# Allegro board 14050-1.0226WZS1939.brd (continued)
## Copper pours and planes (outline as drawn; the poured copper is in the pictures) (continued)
1D35V_VGA_S0 on TOP: 50.88,96.26 50.75,96.39 48.62,96.39 48.54,96.46 48.54,96.97 48.64,97.07 50.35,97.07 50.47,97.2 50.47,98.09 50.29,98.28 48.82,98.28 48.7,98.4 48.7,108.06 48.79,108.15 50.22,108.15 50.37,108 50.37,105.8 50.94,105.22 50.94,103.41 50.78,103.24 50.77,103.24 50.36,102.84 50.36,101.84 49.97,101.45 49.97,99.67 50.23,99.41 50.8,99.41 50.98,99.59 50.98,100.93 51.11,101.06 51.87,101.06 52.71,100.22 52.71,96.67 52.3,96.26 ; 9 cut-outs
1D35V_VGA_S0 on TOP: 58.07,73.15 56.17,75.06 53.5,75.06 51.47,77.09 49.94,77.09 48.42,78.61 48.42,85.6 48.45,85.63 48.45,86.39 48.39,86.46 48.39,87.62 48.59,87.83 48.59,90.85 48.7,90.95 49.33,90.95 49.76,91.38 51.11,91.38 51.64,90.85 51.64,90.01 53.09,88.56 53.09,87.52 52.58,87.01 51.87,87.01 51.21,86.36 51.21,83.19 53.37,81.03 62.01,81.03 62.39,80.64 62.39,78.36 63.66,77.09 65.44,77.09 65.57,76.96 65.57,73.79 64.93,73.15 ; 9 cut-outs
1D35V_VGA_S0 on BOTTOM: 48.55,83.44 48.42,83.57 48.42,85.93 48.59,86.1 48.59,90.04 48.95,90.4 48.95,90.82 49.13,91 49.62,91 49.99,90.63 50.86,90.63 50.86,90.65 51.37,91.16 52.17,91.16 52.66,90.67 52.66,89.55 52.17,89.07 51.64,89.07 51.46,88.89 51.46,88.21 51.87,87.8 52.48,87.8 52.86,88.18 53.29,88.18 53.44,88.03 53.44,86.38 53.29,86.23 53.09,86.23 52.58,86.74 51.92,86.74 51.64,86.46 51.64,85.85 51.87,85.62 52.12,85.62 52.3,85.8 52.66,85.8 52.73,85.72 52.73,84.6 52.75,84.59 52.75,83.7 52.48,83.44 ; 3 cut-outs
1D35V_VGA_S0 on BOTTOM: 52,94.97 50.57,96.39 48.77,96.39 48.59,96.57 48.59,99.23 48.77,99.41 50.5,99.41 50.68,99.59 50.68,100.12 48.85,101.95 48.85,105.86 49.05,106.06 50.8,106.06 51.18,105.68 51.18,101.65 52.61,100.22 52.61,95.17 52.4,94.97 ; 1 cut-out
1D35V_VGA_S0 on BOTTOM: 48.7,111.99 48.57,112.12 48.57,118.34 48.84,118.61 50.42,118.61 50.55,118.49 50.55,114.17 49.44,113.06 49.44,112.22 49.21,111.99 ; 5 cut-outs
1D35V_VGA_S0 on BOTTOM: 60.51,89.39 60.51,91.42 61.78,92.69 61.78,96.75 61.93,96.9 61.93,96.93 61.96,96.95 62.52,96.95 62.75,97.18 62.75,98.3 62.54,98.5 62.54,99.42 61.52,100.44 61.52,103.61 58.73,106.41 58.73,108.31 58.86,108.44 59.24,108.44 61.4,106.28 61.4,106.15 62.92,104.63 62.92,103.1 63.79,102.23 63.79,101.98 64.04,101.73 64.93,101.73 65.54,102.34 66.48,102.34 67.49,101.33 71.94,101.33 72.19,101.58 72.19,103.89 72.6,104.3 76.05,104.3 76.51,104.75 76.51,106.02 76.64,106.15 77.91,106.15 78.16,106.41 78.92,106.41 79.05,106.28 79.05,104.12 78.67,103.74 78.67,97.52 78.8,97.39 78.8,93.83 78.42,93.45 77.78,93.45 77.02,92.69 71.05,92.69 70.6,93.13 64.76,93.13 61.02,89.39 ; 14 cut-outs
1D35V_VGA_S0 on L3: 52.25,83.79 49.93,86.11 49.56,86.11 48.04,87.63 48.04,99.31 48.17,99.44 48.17,122.68 49.31,123.83 52.61,123.83 53.25,123.19 53.25,116.08 52.23,115.06 52.23,114.68 52.1,114.55 52.1,112.01 51.98,111.89 50.96,111.89 50.83,111.76 50.83,110.24 52.23,108.84 52.23,105.54 51.21,104.52 51.21,102.36 51.98,101.6 51.98,98.68 51.85,98.68 50.96,97.79 50.96,97.28 51.21,97.03 51.85,97.03 51.98,96.9 51.98,96.65 51.85,96.52 51.6,96.52 50.58,95.5 50.58,94.87 49.94,94.23 49.94,91.57 50.33,91.19 51.74,91.19 52.38,90.55 52.38,88.23 52.89,87.73 52.89,85.31 53.39,84.81 55.55,84.81 57.08,86.33 57.71,86.33 58.35,85.69 58.35,84.43 57.7,83.79
1D35V_VGA_S0 on L4: 48.17,83.06 47.6,83.62 47.6,116.22 49.31,117.93 49.31,123.44 49.82,123.95 51.72,123.95 53.12,122.56 66.58,122.56 69.12,120.02 71.28,120.02 79.43,111.86 79.43,106.41 79.43,106.4 79.43,101.98 79.41,101.96 79.41,98.68 82.86,95.23 84.11,95.23 84.62,94.72 84.62,92.08 86.14,90.55 86.14,90.42 86.16,90.4 86.16,85.8 81.31,80.95 74.03,80.95 73.96,80.89 54.91,80.89 52.74,83.06 ; 1 cut-out
62883AGND on BOTTOM: 122.97,71.37 122.84,71.5 122.84,72.52 122.72,72.64 118.78,72.64 118.65,72.52 118.65,71.75 118.52,71.63 117.89,71.63 117.76,71.75 117.76,76.45 118.65,77.34 122.72,77.34 122.84,77.22 122.84,75.18 123.99,74.04 123.99,71.5 123.86,71.37 ; 13 cut-outs
AD+_2 on TOP: 66.58,30.73 66.33,30.99 66.33,34.04 67.6,35.31 67.6,37.21 67.72,37.34 68.61,37.34 68.74,37.21 68.74,31.24 68.23,30.73 ; 6 cut-outs
AD+_TO_SYS on TOP: 57.18,40.26 56.55,40.89 53.75,40.89 53.63,41.02 53.63,42.04 52.87,42.8 52.87,46.23 53.25,46.61 57.18,46.61 57.31,46.48 57.31,45.34 57.44,45.21 57.82,45.21 57.95,45.34 57.95,46.48 58.07,46.61 59.09,46.61 59.22,46.48 59.22,40.39 59.09,40.26 ; 1 cut-out
AD+_TO_SYS on BOTTOM: 56.8,38.86 56.68,38.99 56.68,46.48 56.8,46.61 59.22,46.61 59.34,46.48 59.34,38.99 59.22,38.86
AD_JK on TOP: 54.39,23.5 53.5,24.38 53.5,28.19 54.01,28.7 54.9,28.7 56.29,30.1 56.29,30.86 56.55,31.11 56.55,38.61 56.68,38.73 62.01,38.73 63.41,37.34 67.22,37.34 67.34,37.21 67.34,35.56 66.07,34.29 66.07,27.43 65.44,26.8 61.88,26.8 60.23,25.15 60.23,24.38 59.34,23.5 ; 8 cut-outs
AD_JK on BOTTOM: 54.01,20.57 53.5,21.08 53.5,28.7 53.63,28.83 55.02,28.83 55.53,29.34 55.53,30.73 56.42,31.62 59.47,31.62 59.72,31.37 66.33,31.37 66.45,31.24 66.45,28.19 58.83,20.57
AD_JK on L3: 53.75,32.13 64.68,32.13 65.44,31.37 65.44,29.21 60.36,24.13 54.01,24.13 53.25,24.89 53.25,31.62
AD_JK on L4: 53.5,31.75 64.8,31.75 65.44,31.11 65.44,29.59 60.1,24.26 53.88,24.26 53.25,24.89 53.25,31.5
AUD_DVDD on TOP: 162.29,81.89 162.16,82.02 162.16,83.52 161.63,84.05 160.82,84.05 160.64,84.23 160.64,84.89 160.43,85.09 160.05,85.09 159.93,85.22 159.93,87.1 160.05,87.22 161.98,87.22 162.1,87.11 162.1,85.1 163.18,84.02 163.18,82.3 162.77,81.89 ; 2 cut-outs
BOOT1_PHASE1 on TOP: 121.95,80.77 121.7,81.03 121.7,81.79 121.83,81.92 123.99,81.92 124.11,81.79 124.11,80.9 123.99,80.77
BT+ on TOP: 48.29,61.09 47.02,62.36 42.45,62.36 40.42,64.39 37.37,64.39 37.24,64.52 37.24,66.93 36.99,67.18 30.64,67.18 30.51,67.31 30.51,71.25 30.64,71.37 39.61,71.37 40.34,70.64 41.54,70.64 41.82,70.36 41.82,66.67 42.32,66.17 48.55,66.17 50.2,64.52 51.72,64.52 51.85,64.39 51.85,61.21 51.72,61.09 ; 4 cut-outs
BT+ on BOTTOM: 48.93,61.21 48.67,61.47 48.67,65.28 48.8,65.41 49.82,65.41 50.07,65.66 50.96,65.66 51.85,64.77 51.85,61.47 51.6,61.21
BT+ on BOTTOM: 34.22,68.02 33.84,68.4 33.84,71.12 34.09,71.37 36.81,71.37 37.09,71.09 37.09,68.25 36.86,68.02 ; 2 cut-outs
BT+_R on BOTTOM: 46.9,61.59 45.88,62.61 40.93,62.61 40.67,62.87 40.67,65.66 40.93,65.91 46.52,65.91 47.02,65.41 48.04,65.41 48.17,65.28 48.17,61.72 48.04,61.59
CAGND on TOP: 34.32,29.84 33.43,30.73 33.43,34.8 33.69,35.05 35.72,35.05 36.23,35.56 36.23,38.35 36.36,38.48 38.46,38.48 38.84,38.86 38.84,39.7 39.02,39.88 40.37,39.88 40.5,39.75 40.5,37.52 40.27,37.29 40.27,36.63 40.65,36.25 40.65,34.29 41.13,33.81 41.13,33.35 41.05,33.27 40.6,33.27 39.76,34.11 39.76,34.8 39.5,35.05 37.88,35.05 36.74,33.91 35.85,33.91 35.34,33.4 35.34,32.13 35.59,31.88 37.88,31.88 38.01,31.75 38.01,30.35 37.5,29.84 ; 17 cut-outs
CPU_VCORE on TOP: 41.94,171.7 38.62,175.03 35.44,175.03 35.21,175.26 35.21,178.13 35.64,178.56 42.2,178.56 42.58,178.94 42.58,180.21 45.18,182.82 47.72,182.82 48.17,183.26 48.17,185.8 48.52,186.16 59.47,186.16 60.36,185.27 60.36,179.96 52.1,171.7
CPU_VCORE on BOTTOM: 73.69,156.84 73.57,156.97 73.57,168.4 73.69,168.53 88.55,168.53 88.68,168.4 88.68,159.64 88.55,159.51 78.39,159.51 75.73,156.84 ; 33 cut-outs
CPU_VCORE on L3: 77.88,167 77.88,159.64 78.14,159.38 88.04,159.38 88.17,159.51 88.17,167 88.04,167.13 78.01,167.13
CPU_VCORE on L4: 75.47,175.39 87.28,175.39 88.43,174.24 88.43,159.51 88.17,159.26 77.88,159.26 75.6,156.97 74.58,156.97 74.33,157.23 74.33,157.35 62.9,168.78 50.96,168.78 49.56,170.18 49.56,183.9 49.58,183.91 49.58,185.33 50.17,185.93 64.93,185.93
DC_19V on TOP: 59.85,39.12 59.72,39.24 59.72,46.35 59.98,46.61 63.15,46.61 63.41,46.35 63.41,43.94 63.53,43.81 68.61,43.81 68.74,43.69 68.74,39.24 68.61,39.12 ; 4 cut-outs
DC_19V on TOP: 42.53,70.31 42.37,70.46 42.37,71.35 42.68,71.65 42.68,72.54 42.81,72.67 43.8,72.67 44.53,71.93 48.65,71.93 48.72,71.86 48.72,70.71 48.32,70.31 ; 3 cut-outs
DC_19V on BOTTOM: 59.98,38.86 59.85,38.99 59.85,46.35 59.98,46.48 63.03,46.48 63.53,45.97 63.53,39.62 62.77,38.86
DCBATOUT on TOP: 112.17,19.68 111.03,20.83 111.03,26.92 111.29,27.18 114.08,27.18 114.21,27.05 114.21,19.81 114.08,19.68
DCBATOUT on TOP: 97.44,57.4 94.65,60.2 90.46,60.2 88.81,61.85 88.81,64.9 88.93,65.02 90.46,65.02 90.58,64.9 90.58,62.87 91.47,61.98 95.92,61.98 98.59,59.31 103.67,59.31 103.79,59.18 103.79,57.48 103.72,57.4
DCBATOUT on TOP: 51.09,46.48 50.71,46.86 50.71,50.62 50.96,50.88 55.68,50.88 57.56,49 57.56,47.37 57.31,47.12 53.12,47.12 52.48,46.48 ; 1 cut-out
DCBATOUT on TOP: 42.32,66.67 42.07,66.93 42.07,69.65 42.43,70 48.65,70 48.93,69.72 48.93,67.06 48.55,66.67 ; 2 cut-outs
DCBATOUT on TOP: 7.02,151.13 6.89,151.26 6.89,154.31 10.45,157.86 10.45,162.18 7.53,165.1 7.53,167.77 9.69,169.93 12.99,169.93 13.37,169.54 13.37,161.93 14.13,161.16 14.13,159 13.11,157.99 13.11,151.26 12.99,151.13
DCBATOUT on TOP: 38.54,52.3 38.29,52.55 38.29,58.37 38.46,58.55 42.27,58.55 42.53,58.29 42.53,54.38 42.81,54.1 42.81,52.5 42.6,52.3 ; 2 cut-outs
DCBATOUT on TOP: 121.32,86.23 121.19,86.36 121.19,91.69 122.21,92.71 122.21,97.54 122.33,97.66 128.68,97.66 129.07,98.04 129.07,99.31 129.57,99.82 133.26,99.82 133.64,99.44 133.64,95.76 133.89,95.5 139.23,95.5 139.35,95.38 139.35,90.17 139.23,90.04 138.46,90.04 138.08,89.66 138.08,87.63 137.96,87.5 135.54,87.5 134.34,86.3 125.19,86.3 125.13,86.23 ; 4 cut-outs
DCBATOUT on TOP: 49.03,127.18 46.06,130.15 46.06,131.57 46.97,132.49 55.94,132.49 56.55,131.88 56.55,127.69 56.04,127.18
DCBATOUT on TOP: 68.51,26.19 68.33,26.37 68.33,28.93 68.82,29.41 69.76,29.41 70.09,29.08 70.09,26.44 69.83,26.19 ; 2 cut-outs
DCBATOUT on TOP: 22.44,162.31 21.88,162.86 21.88,166.17 22.13,166.42 24.65,166.42 25.05,166.01 25.05,162.56 24.8,162.31
DCBATOUT on TOP: 67.95,44.42 66.84,45.54 66.15,45.54 65.87,45.82 65.87,47.29 66.78,48.21 69.25,48.21 69.6,47.85 69.6,44.91 69.12,44.42 ; 1 cut-out
DCBATOUT on TOP: 19.21,191.52 19.08,191.64 19.08,201.68 19.34,201.93 22.64,201.93 22.89,202.18 22.89,208.91 23.4,209.42 40.04,209.42 42.4,211.79 42.4,218.44 42.55,218.59 48.57,218.59 48.93,218.24 48.93,209.68 46.9,207.65 46.9,202.06 50.07,202.06 50.2,201.93 50.2,191.64 50.07,191.52 44.74,191.52 44.61,191.64 44.61,196.22 41.56,199.26 41.56,202.44 41.18,202.82 28.1,202.82 27.59,202.31 27.59,198.88 24.93,196.22 24.93,191.64 24.8,191.52 ; 4 cut-outs
DCBATOUT on BOTTOM: 89.19,62.87 88.81,63.25 88.81,66.87 84.23,71.44 73.88,71.44 73.19,70.74 68.74,70.74 68.61,70.87 68.61,77.98 69.25,78.61 83.09,78.61 89.7,85.22 102.78,85.22 105.06,87.5 111.54,87.5 113.19,85.85 120.68,85.85 121.19,86.36 121.19,91.69 122.21,92.71 122.21,97.54 122.33,97.66 137.07,97.66 138.59,96.14 138.59,87.88 130.84,80.14 110.27,80.14 109.51,79.38 93,79.38 91.47,77.85 91.47,73.79 90.33,72.64 90.58,72.39 90.58,63.25 90.2,62.87 ; 6 cut-outs
DCBATOUT on BOTTOM: 113.32,4.32 113.19,4.45 113.19,20.32 111.03,22.48 111.03,26.8 111.16,26.92 117.76,26.92 118.52,26.16 118.52,14.1 119.54,13.08 119.54,9.78 117.76,8 117.76,4.39 117.69,4.32
DCBATOUT on BOTTOM: 36.99,51.94 36.86,52.07 36.86,53.04 38.21,54.38 42.93,54.38 42.96,54.36 42.96,52.07 42.83,51.94 ; 1 cut-out
DCBATOUT on BOTTOM: 16.67,163.19 16.29,163.58 12.73,163.58 8.92,167.39 8.92,168.66 9.94,169.67 9.94,186.31 14.13,190.5 14.13,195.58 20.99,202.44 20.99,206.5 21.5,207.01 35.34,207.01 37.37,209.04 39.66,209.04 42.45,211.84 42.45,218.72 43.26,219.53 48.83,219.53 49.31,219.05 49.31,216.66 49.69,216.28 49.69,215.39 50.2,214.88 54.14,214.88 54.26,214.76 54.26,209.42 54.14,209.3 50.07,209.3 49.82,209.04 49.82,197.74 49.44,197.36 41.31,197.36 41.18,197.49 41.18,202.31 40.8,202.69 28.61,202.69 28.23,202.31 28.23,195.83 23.15,190.75 23.15,188.09 20.48,185.42 20.48,171.2 23.78,167.89 23.78,163.58 23.4,163.19 ; 2 cut-outs
DCBATOUT on BOTTOM: 34.96,126.75 32.67,129.03 32.67,132.72 29.37,136.02 16.92,136.02 15.78,137.16 15.78,139.83 15.91,139.95 34.7,139.95 42.58,132.08 49.06,132.08 49.56,131.57 49.56,127 49.31,126.75
DCBATOUT on L3: 113.19,28.07 113.19,24.51 111.54,22.86 68.61,22.86 68.49,22.99 68.49,28.07 68.61,28.19 113.06,28.19
DCBATOUT on L3: 6.89,155.96 6.89,151.26 7.15,151 9.56,151 10.07,151.51 10.07,165.48 12.99,168.4 12.99,169.54 12.61,169.93 9.81,169.93 8.42,168.53 8.42,157.48
DCBATOUT on L3: 49.82,43.94 46.9,46.86 40.67,46.86 37.88,49.66 37.88,53.78 38.13,54.04 50.52,54.04 54.01,50.55 68.74,50.55 69.25,50.04 69.25,45.72 67.47,43.94
DCBATOUT on L4: 15.02,140.72 15.02,146.43 14.13,147.32 14.13,150.88 11.84,153.16 11.84,166.75 12.86,167.77 12.86,169.67 12.61,169.93 9.56,169.93 8.67,169.04 7.02,169.04 6.64,168.66 6.64,163.83 8.67,161.8 8.67,158.12 6.64,156.08 6.64,134.24 7.02,133.86 19.21,133.86 19.46,134.11 19.46,136.27
DCBATOUT on L4: 70.52,26.16 68.61,26.16 66.84,27.94 66.84,47.73 69.73,50.62 69.73,60.71 67.8,62.64 67.8,65.02 67.42,65.41 63.15,65.41 62.77,65.79 62.77,65.91 61.76,66.93 58.33,66.93 56.23,64.83 44.67,64.83 44.48,65.02 44.48,69.47 44.99,69.98 53.75,69.98 57.06,73.28 66.96,73.28 68.61,71.63 73.31,71.63 76.23,68.71 76.23,47.37 73.69,44.83 72.55,44.83 71.92,44.2 71.92,27.56
GFX_VCORE on TOP: 55.02,186.94 54.39,187.58 54.39,202.18 57.18,204.98 65.31,204.98 65.44,204.85 65.44,195.83 56.55,186.94
GFX_VCORE on BOTTOM: 74.33,168.91 74.2,169.04 74.2,171.96 74.96,172.72 74.96,173.99 63.28,185.67 56.04,185.67 55.02,186.69 55.02,196.34 55.28,196.6 66.58,196.6 70.26,200.28 101.51,200.28 103.67,198.12 103.67,176.53 101.95,174.82 90.65,174.82 88.68,172.85 88.68,169.04 88.55,168.91 ; 31 cut-outs
GFX_VCORE on L3: 73.95,176.02 73.95,171.2 76.36,168.78 87.92,168.78 88.17,169.04 88.17,177.04 86.65,178.56 76.49,178.56
ISW_1 on BOTTOM: 47.3,44.02 46.57,44.75 44.91,44.75 44.79,44.88 44.79,50.22 44.91,50.34 48.47,50.34 48.6,50.22 48.6,44.17 48.45,44.02
LX on TOP: 39.38,40.51 37.05,42.84 37.05,49.95 38.41,51.31 41.44,51.31 41.66,51.08 41.66,43.87 40.77,42.98 40.77,40.56 40.72,40.51
LX on BOTTOM: 37.37,43.18 37.24,43.31 37.24,48.77 37.37,48.9 41.1,48.9 41.54,48.46 41.54,43.48 41.23,43.18
MCT_R on TOP: 60.23,9.65 60.1,9.78 60.1,14.1 60.23,14.22 62.52,14.22 62.77,13.97 63.79,13.97 63.91,14.1 63.91,17.4 64.04,17.53 66.33,17.53 66.45,17.4 66.45,14.17 65.06,12.78 65.06,10.54 64.42,9.91 62.77,9.91 62.52,9.65 ; 2 cut-outs
MPV18 on BOTTOM: 78.75,87.3 78.62,87.43 78.62,92.23 78.42,92.44 78.01,92.44 77.91,92.54 77.91,93.1 78.01,93.2 78.54,93.2 78.97,92.77 78.97,92.28 79.18,92.08 79.18,91.04 79.3,90.91 79.3,87.41 79.2,87.3
PWR_1D8V_LX on TOP: 105.95,64.14 105.82,64.26 105.82,66.04 105.57,66.29 101.51,66.29 101.38,66.42 101.38,69.72 101.51,69.85 107.09,69.85 107.35,69.6 107.35,64.39 107.09,64.14 ; 1 cut-out
PWR_1D8V_LX on BOTTOM: 102.9,66.55 102.78,66.67 102.78,69.6 102.9,69.72 104.68,69.72 104.94,69.47 104.94,66.8 104.68,66.55
PWR_1D8V_SNB on BOTTOM: 105.7,66.29 105.57,66.42 105.57,69.34 105.7,69.47 106.97,69.47 107.09,69.34 107.09,66.42 106.97,66.29 ; 1 cut-out
PWR_3D3V_PHASE2 on TOP: 125.38,5.21 124.24,6.35 124.24,13.84 124.75,14.35 128.3,14.35 129.19,13.46 129.19,5.84 128.56,5.21
PWR_3D3V_PHASE2 on BOTTOM: 126.09,5.84 126.02,5.92 126.02,7.82 127.01,8.81 127.01,10.31 126.25,11.07 124.32,11.07 124.24,11.15 124.24,14.48 124.29,14.53 128.89,14.53 129.19,14.22 129.19,6.15 128.89,5.84
PWR_3D3V_SNB on BOTTOM: 124.47,8.79 124.42,8.84 124.42,9.42 124.29,9.55 123.15,9.55 123.1,9.6 123.1,10.44 123.15,10.49 125.76,10.49 126.45,9.8 126.47,9.8 126.47,9.09 126.17,8.79
PWR_5V_PHASE1 on TOP: 124.8,14.94 124.11,15.62 124.11,24.38 124.87,25.15 128.81,25.15 129.42,24.54 129.42,15.16 129.19,14.94
PWR_5V_PHASE1 on BOTTOM: 124.24,14.86 124.11,14.99 124.11,18.85 124.34,19.08 126.14,19.08 126.37,19.3 126.37,21.01 126.55,21.18 127.57,21.18 127.8,21.41 127.8,22.1 127.39,22.5 127.39,23.04 127.21,23.22 126.19,23.22 126.12,23.29 126.12,24.89 126.13,24.9 126.13,25.01 126.4,25.27 129.07,25.27 129.45,24.89 129.45,15.11 129.19,14.86
PWR_CHG_PHASE on TOP: 43.09,57.15 42.83,57.4 42.83,58.67 42.71,58.8 40.17,58.8 40.04,58.93 40.04,60.33 39.91,60.45 39.78,60.45 39.66,60.58 39.66,60.96 39.78,61.09 45.75,61.09 46.77,60.07 46.77,57.28 46.64,57.15
PWR_CHG_PHASE on BOTTOM: 40.93,57.15 39.53,58.55 39.53,60.83 39.78,61.09 44.86,61.09 45.12,60.83 45.12,57.53 44.74,57.15
PWR_CPU_SNBNB on TOP: 25.69,192.53 25.43,192.79 25.43,194.56 25.94,195.07 27.21,195.07 27.47,194.82 27.47,192.66 27.34,192.53 ; 1 cut-out
PWR_CPU_SNBVDD1 on TOP: 42.07,192.53 41.94,192.66 41.94,194.82 42.2,195.07 43.59,195.07 43.85,194.82 43.85,192.66 43.72,192.53 ; 1 cut-out
PWR_CPU_SW1 on TOP: 35.72,185.04 35.59,185.17 35.59,194.94 35.72,195.07 41.31,195.07 41.44,194.94 41.44,191.39 41.56,191.26 48.42,191.26 48.55,191.13 48.55,188.72 44.86,185.04
PWR_CPU_SW1 on BOTTOM: 35.47,185.29 35.21,185.55 35.21,194.56 35.72,195.07 41.18,195.07 41.31,194.94 41.31,190.88 41.94,190.25 44.48,190.25 45.75,188.98 45.75,186.31 44.74,185.29
PWR_CPU_SW2 on TOP: 20.99,185.04 19.59,186.44 19.59,191.13 19.72,191.26 27.97,191.26 28.1,191.39 28.1,194.94 28.23,195.07 33.69,195.07 33.82,194.94 33.82,185.17 33.69,185.04
PWR_CPU_SW2 on BOTTOM: 24.29,185.04 23.78,185.55 23.78,187.96 25.05,189.23 27.47,189.23 27.72,189.48 27.72,194.82 27.97,195.07 33.69,195.07 33.82,194.94 33.82,185.29 33.56,185.04
PWR_DCBATOUT_1D8V on TOP: 104.17,57.4 104.05,57.53 104.05,59.18 104.3,59.44 104.3,63.12 104.43,63.25 106.08,63.25 106.21,63.12 106.21,61.72 106.84,61.09 106.84,57.53 106.71,57.4
PWR_DCBATOUT_3V on BOTTOM: 118.52,4.27 118.4,4.39 118.4,7.7 118.45,7.75 119.64,7.75 119.87,7.52 122.21,7.52 123.32,8.64 123.32,9.27 123.38,9.32 124.06,9.32 124.11,9.27 124.11,8.56 124.32,8.36 125.28,8.36 125.51,8.13 125.51,4.34 125.43,4.27
PWR_DCBATOUT_5V on TOP: 115.1,19.56 114.97,19.68 114.97,27.18 115.1,27.3 122.46,27.3 123.73,26.04 123.73,24.64 122.21,23.11 119.67,23.11 116.11,19.56
PWR_DCBATOUT_5V on BOTTOM: 123.55,20.8 123.48,20.88 123.48,21.39 121.04,23.83 119.64,23.83 119.46,24 119.46,25.63 120.23,26.39 124.49,26.39 125.51,25.37 125.51,22.07 125.43,22 124.42,22 124.19,21.77 124.19,20.93 124.06,20.8
PWR_DCBATOUT_VDDP on TOP: 25.31,157.73 25.18,157.86 25.18,161.67 25.56,162.05 25.56,165.99 25.94,166.37 28.86,166.37 29.24,165.99 29.24,164.08 29.62,163.7 32.67,163.7 33.05,163.32 33.05,157.99 32.8,157.73 ; 2 cut-outs
PWR_DCBATOUT_VDDP on BOTTOM: 24.77,158.5 24.53,158.73 24.53,162.2 24.64,162.31 27.34,162.31 27.72,161.93 27.72,158.62 27.59,158.5
PWR_GFX_SNB1 on BOTTOM: 52.74,218.57 52.61,218.69 52.61,220.85 52.69,220.93 54.44,220.93 54.52,220.85 54.52,218.69 54.39,218.57 ; 1 cut-out
PWR_GFX_SW1 on TOP: 54.64,211.58 54.52,211.71 54.52,215.77 54.77,216.03 66.96,216.03 67.22,215.77 67.22,214.76 64.04,211.58
PWR_GFX_SW1 on BOTTOM: 54.77,210.95 54.64,211.07 54.64,215.39 54.39,215.65 52.74,215.65 52.61,215.77 52.61,217.04 52.74,217.17 54.64,217.17 54.9,217.42 54.9,221.11 55.15,221.36 67.34,221.36 67.47,221.23 67.47,215.26 63.15,210.95
PWR_VDDP_BOOT on TOP: 19.77,157.68 19.77,158.85 21.72,160.81 23.05,160.81 23.38,160.48 23.38,159.87 23.2,159.69 22.72,159.69 20.71,157.68
PWR_VDDP_PHASE on TOP: 29.62,149.22 29.5,149.35 29.5,154.56 29.75,154.81 32.8,154.81 33.31,155.32 33.31,161.54 33.56,161.8 37.24,161.8 38.26,160.78 38.26,152.65 34.83,149.22 ; 2 cut-outs
PWR_VDDP_SNB on TOP: 30.77,155.19 30.64,155.32 30.64,157.1 30.77,157.23 32.93,157.23 33.05,157.1 33.05,155.32 32.93,155.19 ; 1 cut-out
PWR_VDDQ_PHASE on TOP: 142.73,79.45 142.73,80.59 143.85,81.71 144.51,81.71 144.71,81.51 144.71,81.13 143.04,79.45
PWR_VDDQ_PHASE on TOP: 140.5,91.95 140.37,92.08 140.37,95.63 140.24,95.76 135.42,95.76 135.29,95.89 135.29,99.06 136.69,100.46 142.78,100.46 145.96,97.28 145.96,92.08 145.83,91.95
PWR_VDDQ_VTTIN on TOP: 141.54,79.45 141.51,79.48 141.51,80.26 139.76,82.02 136.76,82.02 136.46,82.32 136.46,83.85 136.53,83.92 142.07,83.92 142.12,83.87 142.12,82.5 141.31,81.69 141.31,80.98 141.71,80.57 141.71,79.48 141.69,79.45
PWR_VGA_CORE_PHASE1 on TOP: 113.83,94.36 113.7,94.49 113.7,100.2 113.76,100.27 113.76,103.44 114.46,104.14 119.79,104.14 120.81,105.16 126.02,105.16 126.4,104.78 126.4,104.27 126.33,104.2 126.33,103.44 126.4,103.38 126.4,100.46 127.67,99.19 127.67,98.04 127.54,97.92 119.79,97.92 119.54,97.66 119.54,94.49 119.41,94.36
PWR_VGA_CORE_PHASE1 on BOTTOM: 113.95,94.36 113.83,94.49 113.83,104.52 114.46,105.16 125.89,105.16 126.4,104.65 126.4,98.04 126.27,97.92 119.79,97.92 119.54,97.66 119.54,94.61 119.29,94.36
PWR_VGA_CORE_SNB1 on TOP: 120.3,94.74 119.92,95.12 119.92,97.03 120.3,97.41 121.57,97.41 121.95,97.03 121.95,95 121.7,94.74 ; 1 cut-out
SB3V on TOP: 128.99,55.22 128.4,55.8 128.4,57.35 124.11,61.65 124.11,65.66 126.4,67.94 130.13,67.94 131.91,69.72 144.53,69.72 145.65,70.84 145.65,72.34 145.75,72.44 146.41,72.44 146.79,72.06 146.79,69.88 148.04,68.63 149.74,68.63 150.53,67.84 150.53,65.41 150.25,65.13 150.25,64.57 150.12,64.44 149.72,64.44 149.59,64.57 149.59,65.79 148.72,66.65 146.06,66.65 145.19,65.79 145.19,64.52 145.07,64.39 143.42,64.39 143.04,64.77 141.89,64.77 141.64,65.02 141.64,65.91 140.67,66.88 136.1,66.88 134.73,65.51 133.31,65.51 133.03,65.23 130.23,65.23 129.24,64.24 129.24,59.28 129.95,58.57 129.95,56.72 130.23,56.44 130.23,55.37 130.08,55.22 ; 4 cut-outs
SB3V on TOP: 86.52,7.11 86.39,7.24 86.39,10.54 86.52,10.67 88.3,10.67 88.81,11.18 89.57,11.18 89.82,10.92 89.82,9.78 89.06,9.02 89.06,7.37 88.81,7.11 ; 2 cut-outs
SB3V on BOTTOM: 40.8,4.32 39.28,5.84 39.28,7.62 39.53,7.87 40.42,7.87 41.94,6.35 41.94,4.57 41.69,4.32 ; 2 cut-outs
SB3V on BOTTOM: 162.52,187.12 162.01,187.63 162.01,197.03 161.3,197.74 161.3,199.47 163.91,199.47 165.39,197.99 165.39,188.01 164.5,187.12 ; 2 cut-outs
SB3V on BOTTOM: 125.26,206.25 125,206.5 125,209.8 126.27,211.07 127.54,211.07 128.3,210.31 128.3,208.03 128.43,207.9 130.08,207.9 130.34,207.65 130.34,206.38 130.21,206.25 ; 6 cut-outs
SB5V on TOP: 91.6,7.24 91.47,7.37 91.47,9.14 90.97,9.65 90.97,11.05 91.09,11.18 91.6,11.18 91.98,10.79 93.89,10.79 94.39,10.29 94.39,7.49 94.14,7.24 ; 3 cut-outs
SB5V on BOTTOM: 146.59,52.2 146.46,52.32 146.46,54.48 146.72,54.74 147.99,54.74 148.12,54.61 148.12,52.32 147.99,52.2
USBVCC01 on TOP: 100.62,16.76 100.36,17.02 100.36,28.75 100.74,29.13 101.63,29.13 102.01,29.51 102.01,38.86 101.76,39.12 100.24,39.12 99.86,39.5 99.86,41.4 100.49,42.04 104.81,42.04 104.94,41.91 104.94,29.72 105.19,29.46 105.82,29.46 105.95,29.34 105.95,27.81 106.08,27.69 108.11,27.69 108.24,27.56 108.24,19.43 107.86,19.05 105.06,19.05 104.94,19.18 104.94,23.11 104.81,23.24 103.41,23.24 103.28,23.11 103.28,17.02 103.03,16.76 ; 3 cut-outs
USBVCC23 on TOP: 169.96,119.63 169.45,120.14 169.45,125.48 169.58,125.6 173.13,125.6 173.64,125.09 173.64,120.02 173.26,119.63 ; 3 cut-outs
USBVCC23 on L3: 165.51,116.46 165.51,99.11 166.24,98.39 168.7,98.39 169.17,97.92 173.26,97.92 173.77,98.42 173.77,111.38 171.99,113.16 171.99,117.86 173.77,119.63 173.77,121.03 173.52,121.28 170.34,121.28
USBVCCTP on TOP: 29.12,4.7 28.66,5.16 26.45,5.16 26.09,5.51 26.09,7.06 26.27,7.24 26.93,7.24 27.34,6.83 29.78,6.83 30.13,6.48 30.13,5.08 29.75,4.7
USBVCCTP on BOTTOM: 24.8,5.33 24.67,5.46 24.67,9.02 24.8,9.14 27.21,9.14 27.47,8.89 27.47,8 26.96,7.49 26.96,5.46 26.83,5.33
V_1P05_LAN on BOTTOM: 34.32,9.83 33.51,10.64 33.51,13.56 34.73,14.78 35.75,14.78 35.97,14.55 35.97,12.65 36.23,12.4 38.41,12.4 38.44,12.37 38.44,11.53 39.07,10.9 39.73,10.9 40.55,11.71 40.55,16.51 40.42,16.64 40.42,17.65 40.55,17.78 41.31,17.78 41.92,17.17 41.92,11.61 40.14,9.83 ; 8 cut-outs
V_1P5_PWR on TOP: 32.16,142.88 31.66,143.38 29.88,143.38 29.24,144.02 27.72,144.02 27.47,144.27 27.47,146.3 27.85,146.69 33.84,146.69 34.15,146.38 34.15,145.92 33.43,145.21 33.43,143 33.31,142.88 ; 9 cut-outs
V_1P8_VDDIO on TOP: 24.42,141.99 24.29,142.11 24.29,145.16 24.04,145.41 22.39,145.41 22.13,145.67 22.13,148.34 22.26,148.46 25.56,148.46 27.34,146.69 27.34,142.11 27.21,141.99
V_3_CARD_BD on TOP: 159.55,143 159.42,143.13 159.42,146.18 159.55,146.3 167.67,146.3 167.8,146.18 167.8,143.13 167.67,143 ; 8 cut-outs
V_3P0_BAT_VREG on TOP: 156.62,120.65 156.5,120.78 156.5,122.94 156.62,123.06 159.67,123.06 159.8,122.94 159.8,120.78 159.67,120.65 ; 4 cut-outs
V_3P3_A on TOP: 88.68,12.45 88.17,12.95 87.66,12.95 87.54,13.08 87.54,16.76 87.79,17.02 88.93,17.02 89.19,16.76 89.19,15.88 89.57,15.49 89.57,13.34 89.7,13.21 89.7,12.57 89.57,12.45 ; 5 cut-outs
V_3P3_A on TOP: 138.08,3.43 137.83,3.68 137.83,5.18 137.75,5.26 136.25,5.26 135.42,6.1 130.59,6.1 130.46,6.22 130.46,12.32 130.59,12.45 132.88,12.45 136.3,9.02 140.24,9.02 140.37,8.89 140.37,5.33 140.5,5.21 142.15,5.21 142.27,5.33 142.27,5.71 142.4,5.84 143.54,5.84 144.05,6.35 144.94,6.35 145.19,6.1 145.19,5.59 145.32,5.46 145.7,5.46 145.83,5.33 145.83,4.45 144.81,3.43 ; 3 cut-outs
V_3P3_A on L3: 136.81,2.03 89.19,2.03 88.17,3.05 88.17,4.95 88.3,5.08 89.82,5.08 90.58,4.32 135.92,4.32 136.94,5.33 136.94,8.76 137.19,9.02 139.23,9.02 139.61,8.64 139.61,4.83
V_3P3_A on L4: 87.92,16 87.66,15.75 87.66,12.06 87.03,11.43 87.03,7.62 87.54,7.11 87.54,5.08 87.92,4.7 87.92,3.56 88.17,3.3 89.44,3.3 89.7,3.56 92.49,3.56 93.25,4.32 93.25,14.86 92.11,16
V_3P3_LAN on L3: 37.93,6.12 30.92,6.12 29.37,7.67 29.37,9.91 30.04,10.58 31.36,10.58 37.75,16.97 37.75,17.63 38.34,18.21 39.23,18.21 41.46,15.98 41.46,9.65
V_3P3_PCIVAUX on TOP: 117.64,222.25 117.51,222.38 117.51,223.14 120.18,225.81 121.7,225.81 121.95,225.55 121.95,224.28 121.83,224.16 121.45,224.16 119.54,222.25 ; 1 cut-out
V_3P3_PCIVAUX on TOP: 117.51,202.95 117.38,203.07 117.38,205.61 117.51,205.74 121.57,205.74 121.95,205.36 121.95,203.2 121.7,202.95 ; 2 cut-outs
V_3P3_PCIVAUX on BOTTOM: 121.95,202.44 121.32,203.07 121.32,205.61 121.45,205.74 132.37,205.74 132.49,205.61 132.49,202.69 132.24,202.44 ; 6 cut-outs
V_3P3_PCIVAUX on L3: 120.94,202.69 121.06,202.56 122.21,202.56 122.33,202.69 122.33,205.74 122.21,205.87 121.06,205.87 120.94,205.74
V_5_LCD1 on BOTTOM: 34.32,106.65 34.07,106.91 33.92,106.91 33.59,107.24 32.82,107.24 32.8,107.26 32.8,108.61 32.88,108.69 35.24,108.69 35.72,108.2 35.72,106.76 35.62,106.65 ; 1 cut-out
V_5_LCD2 on BOTTOM: 36.48,106.55 36.36,106.68 36.36,109.22 36.86,109.73 38.26,109.73 38.39,109.6 38.39,108.84 39.15,108.08 39.15,106.68 39.02,106.55 ; 2 cut-outs
V_5HDD on BOTTOM: 4.86,191.13 4.73,191.26 4.73,196.6 5.88,197.74 5.88,201.73 5.98,201.83 13.47,201.83 13.62,201.68 13.62,193.78 13.39,193.55 10.57,193.55 8.16,191.13 ; 4 cut-outs
V_5P0_A on TOP: 85.76,30.35 84.49,31.62 84.49,33.27 84.5,33.29 84.5,34.48 85.55,35.53 90.13,35.53 91.47,34.19 91.47,30.48 91.35,30.35
V_5P0_A on TOP: 144.13,7.75 144.13,7.8 143.31,8.61 143.31,9.3 143.54,9.53 144.31,9.53 144.91,8.92 144.91,7.8 144.86,7.75
V_5P0_A on TOP: 97.23,10.91 95.26,12.88 92.03,12.88 91.68,12.52 90.25,12.52 90.2,12.57 90.2,13.61 90.1,13.72 90.1,14.05 90.94,14.88 95.44,14.88 98.31,12.01 98.31,11.63 97.58,10.91 ; 2 cut-outs
V_5P0_A on TOP: 130.59,16.51 130.46,16.64 130.46,22.61 130.72,22.86 135.42,22.86 136.43,23.88 138.34,23.88 138.72,23.5 138.72,20.07 138.59,19.94 136.18,19.94 132.75,16.51 ; 2 cut-outs
V_5P0_A on BOTTOM: 140.88,7.11 139.35,8.64 139.35,10.54 136.94,12.95 136.94,23.24 137.07,23.37 139.73,23.37 139.86,23.24 139.86,13.84 144.69,9.02 144.69,7.37 144.43,7.11
V_5P0_A on BOTTOM: 87.69,31.11 86.11,32.69 86.11,34.95 86.39,35.23 89.26,35.23 89.7,34.8 89.7,31.37 89.44,31.11
V_5P0_HDMI_CONN on TOP: 107.6,34.16 107.48,34.29 107.48,35.94 107.22,36.2 107.22,40.39 108.75,41.91 114.84,41.91 114.97,41.78 114.97,40.89 114.84,40.77 109.13,40.77 108.75,40.39 108.75,34.29 108.62,34.16 ; 2 cut-outs
V_19_INV on TOP: 43.39,37.59 43.26,37.72 43.26,49.12 43.31,49.17 43.31,50.77 43.85,51.31 47.53,51.31 47.79,51.05 47.79,50.15 48.29,49.65 50.2,49.65 50.33,49.53 50.33,48.01 49.82,47.5 49.82,41.78 49.31,41.27 47.38,41.27 46.52,40.41 46.52,37.72 46.39,37.59 ; 1 cut-out
VGA_CORE on TOP: 83.24,95.48 83.24,95.61 81.46,97.39 81.46,97.9 81.97,98.4 81.97,98.79 81.46,99.29 81.46,99.8 81.97,100.31 81.97,100.56 81.46,101.07 81.46,101.71 81.97,102.21 81.97,102.47 81.84,102.6 81.84,102.85 81.97,102.98 82.35,102.98 82.86,102.47 82.86,102.21 82.23,101.58 82.23,101.07 82.86,100.44 82.86,100.31 82.23,99.67 82.23,99.42 82.35,99.29 82.35,99.17 82.86,98.66 82.86,98.53 83.11,98.28 83.5,98.28 83.62,98.4 83.75,98.4 83.75,98.91 83.24,99.42 83.24,99.67 83.75,100.18 83.75,100.69 83.24,101.2 83.24,101.45 83.75,101.96 83.75,103.23 84.26,103.74 85.4,103.74 85.65,103.48 85.65,103.23 85.02,102.6 85.02,102.34 86.16,101.2 86.16,99.42 86.67,98.91 86.67,98.28 86.16,97.77 87.31,96.63 87.31,95.99 87.05,95.74 86.67,95.74 85.78,96.63 85.02,96.63 83.88,95.48
VGA_CORE on TOP: 79.56,95.36 79.43,95.48 79.43,95.61 79.94,96.12 79.94,96.75 79.81,96.88 79.3,96.88 79.18,97.01 79.18,99.42 79.43,99.67 79.43,100.31 79.3,100.44 79.3,103.48 79.43,103.61 79.69,103.61 80.83,102.47 80.83,102.21 80.29,101.68 80.29,101.22 80.7,100.82 80.7,100.18 80.32,99.8 80.32,99.17 80.78,98.71 80.78,98.23 80.32,97.77 80.32,97.26 80.83,96.75 80.83,96.25 79.94,95.36
VGA_CORE on TOP: 105.95,97.03 105.7,97.28 105.7,115.7 106.08,116.08 119.29,116.08 120.81,114.55 123.35,114.55 123.86,114.05 123.86,110.62 123.22,109.98 115.48,109.98 114.46,108.97 114.46,107.95 113.19,106.68 113.19,97.28 112.94,97.03
VGA_CORE on BOTTOM: 85.27,93.93 85.07,94.14 85.07,94.67 84.77,94.98 83.11,94.98 82.86,95.23 82.86,96.5 83.5,97.13 83.5,100.56 83.75,100.82 83.75,102.98 84,103.23 85.15,103.23 85.53,102.85 85.53,102.47 86.04,101.96 86.04,101.2 86.26,100.97 86.26,100.56 86.19,100.49 85.6,100.49 85.53,100.56 85.53,101.07 85.4,101.2 84.64,101.2 84.51,101.07 84.51,100.56 84.69,100.39 85.07,100.39 85.15,100.31 85.15,99.55 85.27,99.42 86.16,99.42 86.8,98.79 86.8,98.4 86.42,98.02 86.42,97.39 86.67,97.13 86.67,96.68 87.2,96.14 87.2,95.91 87.1,95.81 86.26,95.81 86.01,95.56 86.02,95.55 86.02,94.07 85.88,93.93 ; 15 cut-outs
VGA_CORE on BOTTOM: 105.95,97.03 105.7,97.28 105.7,115.44 106.71,116.46 119.03,116.46 122.72,112.78 122.72,109.86 121.95,109.09 117.51,109.09 113.19,104.78 113.19,97.28 112.94,97.03
VGA_CORE on BOTTOM: 80.45,108.44 80.19,108.69 80.19,109.2 80.07,109.33 80.07,109.96 80.45,110.34 83.24,110.34 84,109.58 84,109.07 83.88,108.95 83.37,108.95 82.86,108.44 ; 5 cut-outs
VGA_CORE on BOTTOM: 79.94,95.61 79.81,95.74 79.81,97.52 79.43,97.9 79.43,99.29 79.3,99.29 78.8,99.8 78.8,102.34 79.69,103.23 80.07,103.23 80.45,102.85 81.59,102.85 81.65,102.79 81.72,102.85 82.35,102.85 82.48,102.72 82.48,98.91 82.35,98.79 82.1,98.79 81.59,98.28 81.59,97.77 81.46,97.64 81.08,97.64 80.7,97.26 80.7,97.03 80.96,96.78 80.96,96.37 80.83,96.25 80.55,96.25 80.45,96.14 80.45,95.74 80.32,95.61 ; 8 cut-outs
VGA_CORE on L3: 82.96,95.76 79.79,98.93 79.79,101.85 79.15,102.49 79.15,105.92 79.79,106.55 79.79,116.2 80.04,116.46 119.03,116.46 122.59,112.9 122.59,109.47 121.57,108.46 114.97,108.46 113.32,106.81 113.32,99.31 109.76,95.76
VGA_CORE on L4: 82.96,95.76 79.79,98.93 79.79,116.2 80.04,116.46 121.57,116.46 122.84,115.19 122.84,110.36 122.46,109.98 118.52,109.98 113.32,104.78 113.32,99.31 109.76,95.76
VOUT_INV on TOP: 26.32,37.72 25.69,38.35 25.69,41.78 27.72,43.81 35.62,43.81 36.41,43.03 36.41,41.66 37.6,40.46 37.6,39.88 37.35,39.62 33.05,39.62 32.29,40.39 32.29,41.53 31.91,41.91 27.59,41.91 27.21,41.53 27.21,39.88 27.59,39.5 30.89,39.5 31.02,39.37 31.02,37.97 30.77,37.72
VOUT_INV on BOTTOM: 27.52,34.72 27.31,34.92 27.31,36.4 27.21,36.5 27.21,42.55 27.47,42.8 36.61,42.8 37.24,42.16 37.24,40.59 37.7,40.13 37.7,39.75 37.5,39.55 36.94,39.55 36.89,39.5 36.89,39.37 34.96,39.37 34.2,38.61 32.29,38.61 30.64,36.96 30.64,34.95 30.41,34.72

Small or netless copper shapes (teardrops, artwork), in the pictures only: 5 on TOP, 5 on BOTTOM

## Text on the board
Ref Des/Silkscreen Bottom: F2:2A/6V | F15:1.5A/6V | F3:1.5A/6V | F1:1.5A/6V | F5:2A/6V | B | A | LAN ID
Ref Des/Silkscreen Top: NORMAL(DEFAULT) | 1-2 | CLR PASSWORD | NC | CLR CMOS | J01010 | SATA HDD | TOUCH | BATTERY | PWRCN1 | F16:3A/32V | F12:2A/6V | F13:1.5A/6V | RJ1 | X4:25MHZ | NGFF_WIFI | Dell P/N:DVXTH | Rev:A00 | SPEAKER | SSUSB2 | SSUSB1 | UHS1 | FAN_CPU | SATAP1 | SATA ODD | CONVERTER | LVDS | X1:48MHZ | DCIN1 | CPU1 | X2:32.768KHZ | LOUT1 | USB3 | USB4 | X5:27MHZ | DIMM1 | PSWD | RTCRST | DIMM2 | F14:2A/6V | For DDR3L Only | F6:1.5A/6V | WEBCAM | M | A | D | E | J | H | F | M2 | Carrizo AIO | 14050-1 | DVXTH | MADE IN TAIWAN
User.27: Board Accuracy Check,Feb 26 18:43:12 2015,Passed | Dummy-Static-No Shape On Layer Check,Feb 26 18:43:13 2015,Passed | Split Plane Check,Nov 25 16:42:05 2014,Passed
User.31: GND | AGND | 1D35V_S3
User.33: ByImpedance:100.0@_REF_L1=("3.5/10.0(L1)")|_REF_L6=("3.5/10.0(L6)")|Type="DP"|_REF_L4=("4.0/9.0(L4)")|_REF_L3=("4.0/9.0(L3)")|imp="100.0" | ByImpedance:110.0@Type="DP"|imp="110.0" | ByImpedance:27.4@Type="SE"|imp="27.4" | ByImpedance:33.0@Type="SE"|imp="33.0" | ByImpedance:34.0@Type="SE"|imp="34.0" | ByImpedance:35.0@Type="SE"|imp="35.0" | ByImpedance:37.5@Type="SE"|imp="37.5" | ByImpedance:39.0@Type="SE"|imp="39.0" | ByImpedance:40.0@_REF_L1=("6.5(L1)")|_REF_L6=("6.5(L6)")|Type="SE"|_REF_L4=("8.5(L4)")|_REF_L3=("8.5(L3)")|imp="40.0" | ByImpedance:42.0@Type="SE"|imp="42.0" | ByImpedance:45.0@_REF_L1=("5.0(L1)")|_REF_L6=("5.0(L6)")|Type="SE"|_REF_L4=("6.5(L4)")|_REF_L3=("6.5(L3)")|imp="45.0" | ByImpedance:48.0@Type="SE"|imp="48.0" | ByImpedance:50.0@_REF_L1=("4.0(L1)")|_REF_L6=("4.0(L6)")|Type="SE"|_REF_L4=("5.0(L4)")|_REF_L3=("5.0(L3)")|imp="50.0" | ByImpedance:52.0@Type="SE"|imp="52.0" | ByImpedance:55.0@Type="SE"|_REF_L4=("4.0(L4)")|_REF_L3=("4.0(L3)")|imp="55.0" | ByImpedance:65.0@Type="DP"|imp="65.0" | ByImpedance:68.0@Type="DP"|imp="68.0" | ByImpedance:70.0@Type="DP"|imp="70.0" | ByImpedance:72.0@_REF_L1=("7.0/8.0(L1)")|_REF_L6=("7.0/8.0(L6)")|Type="DP"|_REF_L3=("7.0/5.0(L3)")|imp="72.0" | ByImpedance:75.0@Type="DP"|imp="75.0" | ByImpedance:80.0@_REF_L1=("5.0/5.0(L1)")|_REF_L6=("5.0/5.0(L6)")|Type="DP"|_REF_L4=("6.0/6.0(L4)")|_REF_L3=("6.0/6.0(L3)")|imp="80.0" | ByImpedance:85.0@_REF_L1=("4.0/4.5(L1)")|_REF_L6=("4.0/4.5(L6)")|Type="DP"|_REF_L4=("5.0/5.5(L4)")|_REF_L3=("5.0/5.5(L3)")|imp="85.0" | ByImpedance:90.0@_REF_L1=("4.0/6.0(L1)")|_REF_L6=("4.0/6.0(L6)")|Type="DP"|_REF_L4=("4.0/5.0(L4)")|_REF_L3=("4.0/5.0(L3)")|imp="90.0" | ByImpedance:93.0@Type="DP"|imp="93.0" | ByImpedance:95.0@Type="DP"|imp="95.0" | LayerIndex:nil | Source:6-1.2-7c.xls | artWorks:("_REF_L3" "_REF_L4" "_REF_L6" "_REF_L1") | gtImpOutlineUsed:BOARD GEOMETRY/PANEL_OUTLINE
User.34: GND | AGND | 1D35V_S3
User.35: 1 | Factory ID:J | CONVERTER | CPU1 | DCIN1 | DIMM1 | Dell: | F15:1.5A/6V | F16:3A/32V | F6:1.5A/6V | LOUT1 | LVDS | NGFF_WIFI | PSWD | PWRCN1 | SATA HDD | SATA ODD | SATAP1 | SPEAKER | SSUSB1 | SSUSB2 | TOUCH | UHS1 | USB3 | USB4 | WEBCAM | X1:48MHZ | X2:32.768KHZ | X4:25MHZ | A | B | C | E | H | J | M | N | P | 14050-SC | 348.02001.00SC | Carrizo AIO | F | MADE IN TAIWAN
User.37: This gerber is just for your reference to find the DP impedance traces in layer L1. | DP IMPEDANCE TABLE: L1 | * - Denotes that WIDTH | is NOT used in this layer | inside board outline. | IMP(Ohm) | 72.0 | 80.0 | 85.0 | 90.0 | 100.0 | WIDTH(mils) | 7.0/8.0 | 5.0/5.0 | 4.0/4.5 | 4.0/6.0 | 3.5/10.0 | TYPE | DP
User.39: This gerber is just for your reference to find the SE impedance traces in layer L1. | SE IMPEDANCE TABLE: L1 | * - Denotes that WIDTH | is NOT used in this layer | inside board outline. | IMP(Ohm) | 40.0 | 45.0 | 50.0 | WIDTH(mils) | 6.5 | 5.0 | 4.0 | TYPE | SE
User.41: This gerber is just for your reference to find the DP impedance traces in layer L3. | DP IMPEDANCE TABLE: L3 | * - Denotes that WIDTH | is NOT used in this layer | inside board outline. | IMP(Ohm) | 72.0 | 80.0 | 85.0 | 90.0 | 100.0 | WIDTH(mils) | 7.0/5.0 | 6.0/6.0 | 5.0/5.5 | 4.0/5.0 | 4.0/9.0 | TYPE | DP
User.43: This gerber is just for your reference to find the SE impedance traces in layer L3. | SE IMPEDANCE TABLE: L3 | * - Denotes that WIDTH | is NOT used in this layer | inside board outline. | IMP(Ohm) | 40.0 | 45.0 | 50.0 | 55.0 | WIDTH(mils) | 8.5 | 6.5 | 5.0 | 4.0 | TYPE | SE
User.45: This gerber is just for you reference to find the differential traces in layer BOTTOM | This gerber is just for you reference to find the differential traces in layer L3 | This gerber is just for you reference to find the differential traces in layer L4 | This gerber is just for you reference to find the differential traces in layer TOP | Note:Refer to DRILL layer for ELLIPSE drill direction | FIGURE | SIZE | 10.0 | 12.0 | 16.0 | 20.0 | 28.0 | 30.0 | 36.0 | 37.0 | 39.0 | 40.0 | 60.0 | 91.0 | 109.0 | 158.0 | 42.0 | 44.0 | 50.0 | 54.0 | 63.0 | 67.0 | 86.0 | 138.0 | 178.0 | 48.0x16.0 | 56.0x24.0 | 60.0x24.0 | 60.0x28.0 | 67.0x28.0 | 67.0x30.0 | 67.0x32.0 | 91.0x28.0 | 156.0x32.0 | 166.0x32.0 | 197.0x178.0 | DRILL CHART: TOP to BOTTOM | ALL UNITS ARE IN MILS | PLATED | NON-PLATED | QTY | 1171 | 2668 | 970 | 40 | 18 | 14 | 8 | 36 | 9 | 4 | 1 | 5 | 2 | 3 | 6 | This gerber is just for your reference to find the DP impedance traces in layer L4. | This gerber is just for your reference to find the DP impedance traces in layer L6. | This gerber is just for your reference to find the SE impedance traces in layer L4. | This gerber is just for your reference to find the SE impedance traces in layer L6. | DP IMPEDANCE TABLE: L4 | DP IMPEDANCE TABLE: L6 | SE IMPEDANCE TABLE: L4 | SE IMPEDANCE TABLE: L6 | * - Denotes that WIDTH | is NOT used in this layer | inside board outline. | Model | Carrizo AIO | ECO | 817473 | PCB_NO | 14050 | VER. | Layer | DRILL | L1 | L2GND | L3 | TMASK | TPLACE | TSILK | TSMD | Designer | MARTIN | Date | 02/27/2015 | IMP(Ohm) | 72.0 | 80.0 | 45.0 | 85.0 | 90.0 | 100.0 | 55.0 | WIDTH(mils) | 6.5 | 8.5 | 5.0 | 4.0 | 6.0/6.0 | 5.0/5.5 | 4.0/5.0 | 4.0/9.0 | *7.0/8.0 | 5.0/5.0 | 4.0/4.5 | 4.0/6.0 | 3.5/10.0 | TYPE | SE | DP | BMASK | BPLACE | BSILK | BSMD | L4 | L5GND | L6
